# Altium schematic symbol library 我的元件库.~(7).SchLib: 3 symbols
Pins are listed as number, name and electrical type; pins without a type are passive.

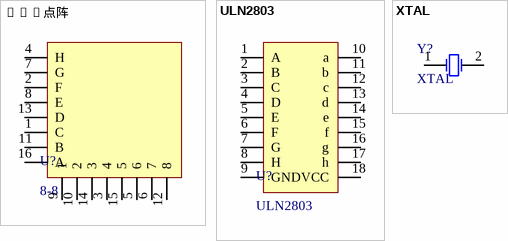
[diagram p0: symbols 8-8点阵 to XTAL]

## 8-8点阵
designator U?, comment 8-8
8-8: RAD
footprint 8-8LED点阵 - duplicate
pins: 1 C, 2 F, 3 4, 4 H, 5 6, 6 7, 7 G, 8 E, 9 1, 10 2, 11 B, 12 8, 13 D, 14 3, 15 5, 16 A

## ULN2803
designator U?
footprint DIP-18
pins: 1 A, 2 B, 3 C, 4 D, 5 E, 6 F, 7 G, 8 H, 9 GND, 10 a, 11 b, 12 c, 13 d, 14 e, 15 f, 16 g, 17 h, 18 VCC

## XTAL
designator Y?
XTAL: 12MHZ
footprint XTAL
pins: 1, 2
